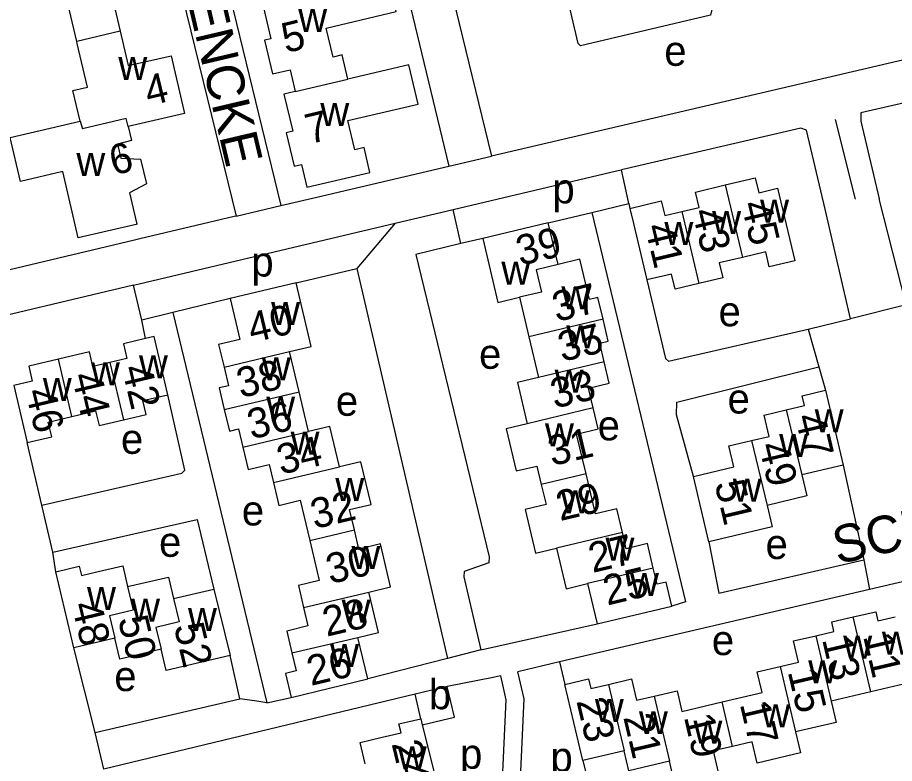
# Model space of a CAD drawing. Extents: x 157646 to 159241, y 379213 to 381217.
# Drawn here: x 158522.9 to 158640, y 380559.1 to 380658.9 of the extents above; entities that cross this region are included whole.
import ezdxf

# ---------------------------------------------------------------- set-up
doc = ezdxf.new("R2010")
doc.units = 0
for name, color, linetype in [('BLT_Basislijn', 7, 'Continuous'), ('BLT_Bebouwing', 7, 'Continuous'), ('BLT_Centroide', 7, 'Continuous'), ('BLT_Huisnummer', 7, 'Continuous'), ('BLT_Huisnummer_ tussenligend', 7, 'Continuous'), ('BLT_Onderverdeling_panden', 7, 'Continuous'), ('BLT_Straatnaam', 7, 'Continuous')]:
    doc.layers.add(name, color=color, linetype=linetype)

msp = doc.modelspace()

# ---------------------------------------------------------------- linework, layer by layer
at = {"layer": 'BLT_Basislijn'}
for p, q in [((158567.85, 380691.44), (158580.51, 380638.99)), ((158545.31, 380686.05), (158558.07, 380633.72)), ((158580.8, 380662.49), (158586.2, 380640.34)), ((158632.13, 380645.23), (158634.79, 380634.57)), ((158580.51, 380638.99), (158586.2, 380640.34)), ((158604.54, 380634.01), (158603.58, 380638.51)), ((158552.08, 380632.31), (158558.07, 380633.72)), ((158582.13, 380628.63), (158581.1, 380633.2)), ((158573.33, 380631.36), (158568.22, 380625.29)), ((158539.5, 380618.39), (158538.4, 380623.1)), ((158551.28, 380621.28), (158543.64, 380619.41)), ((158641.63, 380620.46), (158634.19, 380618.59)), ((158543.64, 380619.41), (158539.5, 380618.39)), ((158543.64, 380619.41), (158556.22, 380567.27)), ((158540.01, 380615.94), (158539.5, 380618.39)), ((158628.53, 380617.18), (158629.95, 380612.15)), ((158629.95, 380612.15), (158630.84, 380609.03)), ((158526.15, 380593.65), (158524.19, 380602.04)), ((158633.21, 380599.03), (158635.96, 380586.38)), ((158527.62, 380587.38), (158526.15, 380593.65)), ((158528.02, 380584.76), (158527.62, 380587.38)), ((158635.96, 380586.38), (158636.73, 380582.42)), ((158636.73, 380582.42), (158595.3, 380572.71)), ((158584.8, 380574.33), (158600.34, 380577.82)), ((158533.27, 380563.29), (158530.41, 380574.61)), ((158584.8, 380574.33), (158580.32, 380573.19)), ((158552.58, 380567.79), (158551.29, 380573.59)), ((158580.32, 380573.19), (158569.67, 380570.44)), ((158595.3, 380572.71), (158589.75, 380571.41)), ((158595.3, 380572.71), (158596.01, 380569.69)), ((158587.42, 380570.87), (158586.42, 380570.64)), ((158534.42, 380558.37), (158533.27, 380563.29)), ((158598.42, 380559.54), (158601.14, 380548.1))]:
    msp.add_line(p, q, dxfattribs=at)
for points in [[(158539.43, 380684.65), (158542.18, 380672.91), (158552.08, 380632.31)], [(158696.38, 380677.06), (158698.13, 380668.11), (158696.65, 380666.48), (158685.35, 380663.55), (158586.2, 380640.34)], [(158615.94, 380661.19), (158615.45, 380659.17), (158598.09, 380655.07), (158597.77, 380655.38), (158596.64, 380660.35), (158593.6, 380660.3), (158592.43, 380664.98), (158580.8, 380662.49)], [(158706.76, 380657.87), (158702.49, 380661.48), (158635.57, 380646.12), (158635.57, 380645.01), (158637.99, 380634.62)], [(158630.78, 380633.26), (158628.29, 380643.8), (158627.54, 380644.08), (158603.58, 380638.51)], [(158558.07, 380633.72), (158562.87, 380634.85), (158580.51, 380638.99)], [(158581.1, 380633.2), (158602.93, 380638.36), (158603.58, 380638.51)], [(158599.6, 380632.81), (158604.54, 380634.01)], [(158604.54, 380634.01), (158604.7, 380633.33)], [(158641.63, 380620.46), (158637.99, 380634.62)], [(158573.33, 380631.36), (158581.1, 380633.2)], [(158593.8, 380631.41), (158599.6, 380632.81)], [(158599.6, 380632.81), (158612.15, 380580.74), (158610.29, 380580.19)], [(158634.19, 380618.59), (158630.78, 380633.26)], [(158552.08, 380632.31), (158551.84, 380632.25), (158539.21, 380629.26)], [(158538.4, 380623.1), (158573.33, 380631.36)], [(158539.21, 380629.26), (158538.5, 380629.1), (158521.88, 380625.14)], [(158585.04, 380629.32), (158582.13, 380628.63)], [(158582.13, 380628.63), (158576.1, 380627.2), (158585.9, 380586.78), (158585.87, 380585.95), (158582.58, 380584.8), (158582.5, 380584.11), (158584.8, 380574.33)], [(158560.1, 380623.38), (158568.22, 380625.29)], [(158568.22, 380625.29), (158580.32, 380573.19)], [(158606.96, 380623.78), (158609.48, 380613.29), (158609.86, 380612.94), (158628.53, 380617.18)], [(158538.4, 380623.1), (158513.99, 380617.28), (158516.27, 380606.04)], [(158628.53, 380617.18), (158634.19, 380618.59)], [(158613.19, 380597.51), (158610.91, 380605.74), (158610.98, 380607.46), (158629.95, 380612.15)], [(158526.15, 380593.65), (158544.86, 380597.96), (158545.25, 380598.33), (158542.98, 380608.44)], [(158527.62, 380587.38), (158546.87, 380591.77), (158549.11, 380582.46)], [(158673, 380587.82), (158672.12, 380590.66), (158636.73, 380582.42)], [(158615.26, 380588.78), (158616.59, 380581.91), (158635.96, 380586.38)], [(158586.42, 380570.64), (158580.28, 380569.43)], [(158587.42, 380570.87), (158588.13, 380567.66), (158587.29, 380549.3), (158588.35, 380544.99)], [(158590.69, 380545.54), (158589.73, 380549.4), (158590.57, 380567.8), (158589.75, 380571.41)], [(158576, 380568.41), (158534.42, 380558.37)], [(158533.27, 380563.29), (158552.58, 380567.79)], [(158556.22, 380567.27), (158554.84, 380567.46), (158552.58, 380567.79)], [(158556.22, 380567.27), (158559.46, 380567.96)]]:
    msp.add_lwpolyline(points, dxfattribs=at)
at = {"layer": 'BLT_Bebouwing'}
for p, q in [((158538.85, 380631.22), (158538.75, 380631.2)), ((158593.8, 380631.41), (158585.04, 380629.32)), ((158560.1, 380623.38), (158551.28, 380621.28)), ((158589.94, 380621.46), (158591.2, 380616.16)), ((158591.2, 380616.16), (158592.49, 380610.74)), ((158560.52, 380608.83), (158559.24, 380614.2)), ((158561.78, 380603.52), (158560.52, 380608.83)), ((158630.84, 380609.03), (158633.21, 380599.03)), ((158522.88, 380607.57), (158524.19, 380602.04)), ((158633.21, 380599.03), (158627.65, 380597.71)), ((158615.26, 380588.78), (158613.19, 380597.51)), ((158530.41, 380574.61), (158528.02, 380584.76)), ((158549.11, 380582.46), (158551.29, 380573.59)), ((158599.06, 380583.18), (158600.34, 380577.82)), ((158600.34, 380577.82), (158610.29, 380580.19)), ((158535.87, 380575.9), (158530.41, 380574.61)), ((158569.67, 380570.44), (158568.35, 380576)), ((158559.46, 380567.96), (158569.67, 380570.44)), ((158598.42, 380559.54), (158596.01, 380569.69)), ((158642.18, 380569.97), (158636.88, 380568.73)), ((158576.78, 380565.13), (158576, 380568.41)), ((158636.88, 380568.73), (158631.58, 380567.49)), ((158603.94, 380560.85), (158598.42, 380559.54))]:
    msp.add_line(p, q, dxfattribs=at)
for points in [[(158532.82, 380673.12), (158538.49, 380674.43), (158540.29, 380666.69), (158538.41, 380666.25), (158539.28, 380662.49), (158535.54, 380661.61), (158536.6, 380657.04)], [(158530.8, 380655.65), (158528.82, 380664.15), (158532.54, 380665.01), (158531.25, 380670.55)], [(158567.04, 380650.62), (158566.27, 380653.85), (158565.05, 380653.56), (158564.13, 380657.44), (158573.47, 380659.65), (158572.23, 380664.9), (158564.1, 380662.97)], [(158560.23, 380662.07), (158555.58, 380660.97), (158556.75, 380656.01), (158555.89, 380655.81), (158556.95, 380651.32), (158559.31, 380651.87), (158560, 380648.96)], [(158536.6, 380657.04), (158537.68, 380652.42), (158543.4, 380653.75), (158545.19, 380646.03), (158537.67, 380644.28)], [(158531.25, 380645), (158530.29, 380649.1), (158532.22, 380649.55), (158530.84, 380655.38), (158530.8, 380655.65)], [(158560, 380648.96), (158558.48, 380648.6), (158559.66, 380643.65), (158558.8, 380643.44), (158559.86, 380638.97), (158560.83, 380639.2), (158561.55, 380636.17), (158569.97, 380638.16), (158569.19, 380641.46), (158567.96, 380641.17), (158567.04, 380645.07), (158576.4, 380647.28), (158575.15, 380652.54), (158567.04, 380650.62)], [(158538.75, 380631.2), (158531, 380629.4), (158528.94, 380638.26), (158523.27, 380636.94), (158521.9, 380642.83), (158531.25, 380645)], [(158537.67, 380644.28), (158538.11, 380642.42), (158536.26, 380641.94), (158536.68, 380640.07), (158539.32, 380639.94), (158540.12, 380636.63), (158537.86, 380635.4), (158538.85, 380631.22)], [(158617.45, 380636.47), (158621.45, 380637.41), (158621.92, 380635.44), (158624.43, 380636.04), (158626.73, 380626.35), (158623.33, 380625.54), (158622.86, 380627.53), (158619.74, 380626.79)], [(158611.64, 380632.94), (158613.94, 380633.48), (158613.45, 380635.52), (158617.45, 380636.47)], [(158604.7, 380633.33), (158608.89, 380634.33), (158609.35, 380632.4), (158611.64, 380632.94)], [(158604.7, 380633.33), (158605.17, 380631.32), (158606.96, 380623.78)], [(158595.13, 380625.86), (158593.8, 380631.41)], [(158585.04, 380629.32), (158587.08, 380620.78), (158589.94, 380621.46)], [(158619.74, 380626.79), (158616.65, 380626.06), (158617.12, 380624.08), (158613.92, 380623.32)], [(158601.11, 380618.52), (158600.42, 380621.45), (158599.3, 380621.18), (158598.02, 380626.55), (158595.13, 380625.86)], [(158613.92, 380623.32), (158610.74, 380622.56), (158610.26, 380624.56), (158606.96, 380623.78)], [(158559.24, 380614.2), (158562.12, 380614.89), (158560.1, 380623.38)], [(158551.28, 380621.28), (158552.58, 380615.82), (158549.76, 380615.15), (158550.48, 380612.12)], [(158601.27, 380612.83), (158600.67, 380615.33), (158601.81, 380615.6), (158601.11, 380618.52)], [(158542.98, 380608.44), (158541.14, 380616.21), (158540.01, 380615.94)], [(158540.01, 380615.94), (158537.03, 380615.23), (158537.5, 380613.27), (158535.23, 380612.73)], [(158535.23, 380612.73), (158532.96, 380612.19), (158532.49, 380614.17), (158528.35, 380613.18)], [(158528.35, 380613.18), (158524.39, 380612.24), (158524.86, 380610.25), (158522.38, 380609.67), (158522.88, 380607.57)], [(158599.79, 380606.66), (158599.15, 380609.32), (158601.95, 380609.99), (158601.27, 380612.83)], [(158550.48, 380612.12), (158551.07, 380609.63), (158549.84, 380609.34), (158550.52, 380606.45)], [(158592.49, 380610.74), (158589.67, 380610.07), (158590.99, 380604.55)], [(158537.05, 380605.07), (158540.08, 380605.79), (158539.64, 380607.65), (158542.98, 380608.44)], [(158625.58, 380606.42), (158628.04, 380607), (158627.73, 380608.29), (158630.84, 380609.03)], [(158530.16, 380605.54), (158533.33, 380606.29), (158533.81, 380604.3), (158537.05, 380605.07)], [(158550.52, 380606.45), (158551.21, 380603.57), (158552.4, 380603.86), (158552.98, 380601.42)], [(158598.85, 380597.84), (158597.58, 380603.18), (158600.46, 380603.86), (158599.79, 380606.66)], [(158620.97, 380602.32), (158623.32, 380602.87), (158622.64, 380605.72), (158625.58, 380606.42)], [(158524.19, 380602.04), (158527.46, 380602.82), (158526.99, 380604.78), (158530.16, 380605.54)], [(158590.99, 380604.55), (158588.18, 380603.89), (158589.53, 380598.24), (158592.27, 380598.9), (158592.86, 380596.42)], [(158565.91, 380598.8), (158564.63, 380604.19), (158561.78, 380603.52)], [(158613.19, 380597.51), (158618.59, 380598.79), (158617.92, 380601.6), (158620.97, 380602.32)], [(158552.98, 380601.42), (158553.7, 380598.42), (158556.52, 380599.09), (158557.09, 380596.7)], [(158567.89, 380590.37), (158567.24, 380593.09), (158570.13, 380593.77), (158568.77, 380599.48), (158565.91, 380598.8)], [(158603.7, 380590.03), (158602.95, 380593.18), (158600.12, 380592.51), (158598.85, 380597.84)], [(158627.65, 380597.71), (158628.32, 380594.9), (158623.03, 380593.64)], [(158557.09, 380596.7), (158557.81, 380593.64), (158560.66, 380594.32), (158561.94, 380588.95)], [(158592.86, 380596.42), (158593.5, 380593.74), (158590.72, 380593.08), (158592.11, 380587.26), (158594.89, 380587.92)], [(158623.03, 380593.64), (158623.71, 380590.79), (158615.26, 380588.78)], [(158569.82, 380582.04), (158572.73, 380582.74), (158571.37, 380588.48), (158568.5, 380587.8), (158567.89, 380590.37)], [(158607.83, 380585.27), (158607.06, 380588.53), (158604.22, 380587.85), (158603.7, 380590.03)], [(158561.94, 380588.95), (158563.21, 380583.59), (158560.41, 380582.92), (158561.11, 380579.97)], [(158594.89, 380587.92), (158596.18, 380582.49), (158599.06, 380583.18)], [(158528.02, 380584.76), (158531.13, 380585.5), (158531.42, 380584.26), (158533.68, 380584.79)], [(158533.68, 380584.79), (158536.94, 380585.56), (158537.6, 380582.78)], [(158610.29, 380580.19), (158609.53, 380583.38), (158608.35, 380583.1), (158607.83, 380585.27)], [(158537.6, 380582.78), (158543.05, 380584.06), (158543.73, 380581.19)], [(158543.73, 380581.19), (158549.11, 380582.46)], [(158568.35, 380576), (158571.1, 380576.65), (158569.82, 380582.04)], [(158561.11, 380579.97), (158561.69, 380577.52), (158558.86, 380576.84), (158559.56, 380573.91)], [(158629.53, 380576.22), (158631.96, 380576.79), (158631.67, 380578.06), (158634.54, 380578.73)], [(158634.54, 380578.73), (158637.54, 380579.43), (158637.82, 380578.23), (158640.12, 380578.76)], [(158542.09, 380574.4), (158536.54, 380573.08), (158535.87, 380575.9)], [(158624.77, 380572.09), (158627.24, 380572.67), (158626.57, 380575.53), (158629.53, 380576.22)], [(158551.29, 380573.59), (158542.76, 380571.57), (158542.09, 380574.4)], [(158559.56, 380573.91), (158560.13, 380571.52), (158558.7, 380571.18), (158559.46, 380567.96)], [(158617.04, 380567.36), (158622.36, 380568.61), (158621.71, 380571.37), (158624.77, 380572.09)], [(158580.28, 380569.43), (158576, 380568.41)], [(158576.97, 380564.32), (158581.25, 380565.34), (158580.28, 380569.43)], [(158596.01, 380569.69), (158599.17, 380570.44), (158599.48, 380569.15), (158601.84, 380569.71)], [(158601.84, 380569.71), (158604.92, 380570.44), (158605.58, 380567.59), (158607.94, 380568.14)], [(158607.94, 380568.14), (158611, 380568.85), (158611.64, 380566.1), (158617.04, 380567.36)], [(158631.58, 380567.49), (158632.25, 380564.63), (158626.82, 380563.36)], [(158571.62, 380562.64), (158574.13, 380563.24), (158573.84, 380564.43), (158576.78, 380565.13)], [(158576.97, 380564.32), (158579.23, 380555.27)], [(158569.35, 380559.08), (158568.67, 380561.93), (158571.62, 380562.64)], [(158626.82, 380563.36), (158627.48, 380560.56), (158621.7, 380559.2), (158621.04, 380562.04), (158618.43, 380561.43)], [(158618.43, 380561.43), (158615.82, 380560.82), (158616.49, 380557.93), (158615.52, 380557.71), (158610.65, 380556.57), (158609.98, 380559.43)], [(158609.98, 380559.43), (158604.57, 380558.17), (158603.94, 380560.85)]]:
    msp.add_lwpolyline(points, dxfattribs=at)
at = {"layer": 'BLT_Onderverdeling_panden'}
for p, q in [((158536.6, 380657.04), (158530.8, 380655.65)), ((158560, 380648.96), (158567.04, 380650.62)), ((158531.25, 380645), (158531.56, 380643.96)), ((158617.45, 380636.47), (158619.74, 380626.79)), ((158611.64, 380632.94), (158613.92, 380623.32)), ((158601.11, 380618.52), (158591.2, 380616.16)), ((158550.48, 380612.12), (158559.24, 380614.2)), ((158530.16, 380605.54), (158528.35, 380613.18)), ((158535.23, 380612.73), (158537.05, 380605.07)), ((158601.27, 380612.83), (158592.49, 380610.74)), ((158550.52, 380606.45), (158560.52, 380608.83)), ((158599.79, 380606.66), (158590.99, 380604.55)), ((158625.58, 380606.42), (158627.65, 380597.71)), ((158552.98, 380601.42), (158561.78, 380603.52)), ((158620.97, 380602.32), (158623.03, 380593.64)), ((158557.09, 380596.7), (158565.91, 380598.8)), ((158598.85, 380597.84), (158592.86, 380596.42)), ((158561.94, 380588.95), (158567.89, 380590.37)), ((158603.7, 380590.03), (158594.89, 380587.92)), ((158607.83, 380585.27), (158599.06, 380583.18)), ((158561.11, 380579.97), (158569.82, 380582.04)), ((158636.88, 380568.73), (158634.54, 380578.73)), ((158559.56, 380573.91), (158568.35, 380576)), ((158629.53, 380576.22), (158631.58, 380567.49)), ((158624.77, 380572.09), (158626.82, 380563.36)), ((158601.84, 380569.71), (158603.94, 380560.85)), ((158607.94, 380568.14), (158609.98, 380559.43)), ((158618.43, 380561.43), (158617.04, 380567.36))]:
    msp.add_line(p, q, dxfattribs=at)
for points in [[(158537.67, 380644.28), (158537.42, 380645.34), (158531.56, 380643.96)], [(158595.13, 380625.86), (158592.18, 380625.15), (158592.89, 380622.16), (158589.94, 380621.46)], [(158537.6, 380582.78), (158538.35, 380579.63), (158535.17, 380578.88), (158535.87, 380575.9)], [(158543.73, 380581.19), (158544.47, 380578.07), (158541.39, 380577.34), (158542.09, 380574.4)], [(158576.78, 380565.13), (158576.97, 380564.32)]]:
    msp.add_lwpolyline(points, dxfattribs=at)

# ---------------------------------------------------------------- texts
at = {"layer": 'BLT_Centroide'}
for s, p in [('w', (158560.39, 380656.94)), ('e', (158609.3, 380652.4)), ('w', (158536.36, 380650.5)), ('w', (158563.34, 380644.34)), ('w', (158530.75, 380637.69)), ('p', (158594.35, 380634.01)), ('w', (158622.09, 380631.42)), ('w', (158615.69, 380629.91)), ('w', (158609.31, 380628.45)), ('p', (158554.13, 380624.23)), ('w', (158587.53, 380623.13)), ('w', (158595.55, 380619.84)), ('w', (158556.77, 380617.75)), ('e', (158616.55, 380617.58)), ('w', (158596.2, 380614.62)), ('e', (158584.55, 380611.9)), ('w', (158532.7, 380609.7)), ('w', (158539.11, 380610.64)), ('w', (158555.53, 380610.34)), ('w', (158594.65, 380608.69)), ('w', (158526.27, 380607.61)), ('w', (158556.12, 380605.12)), ('e', (158565.42, 380605.62)), ('e', (158617.75, 380605.92)), ('w', (158629.39, 380603.41)), ('w', (158593.36, 380601.53)), ('e', (158600.4, 380602.33)), ('e', (158536.71, 380600.53)), ('w', (158559.37, 380600.44)), ('w', (158624.64, 380600.11)), ('w', (158565.35, 380594.22)), ('w', (158618.45, 380594.14)), ('w', (158595.48, 380592.56)), ('e', (158552.86, 380590.96)), ('e', (158541.8, 380586.77)), ('w', (158601.44, 380586.25)), ('e', (158622.83, 380586.47)), ('w', (158567.5, 380585.16)), ('w', (158604.71, 380581.53)), ('w', (158532.17, 380579.64)), ('w', (158538.06, 380578.08)), ('w', (158545.66, 380576.84)), ('w', (158566.19, 380577.97)), ('e', (158615.65, 380573.63)), ('w', (158638.36, 380573.7)), ('w', (158633.2, 380573.14)), ('w', (158564.65, 380572.03)), ('w', (158628.52, 380569.86)), ('e', (158535.82, 380568.82)), ('b', (158577.85, 380566.39)), ('w', (158600.02, 380564.7)), ('w', (158622.25, 380563.97)), ('w', (158605.91, 380563.06)), ('w', (158613.19, 380561.81)), ('w', (158573.69, 380558.34)), ('p', (158582.01, 380558.44)), ('p', (158594.09, 380558.02))]:
    msp.add_text(s, height=4, dxfattribs=at).set_placement(p)
at = {"layer": 'BLT_Huisnummer'}
for s, rotation, p in [('5', 13.692, (158558.72, 380654.08)), ('4', 13.692, (158540.41, 380647.01)), ('7', 13.692, (158561.89, 380641.91)), ('6', 13.692, (158535.72, 380637.73)), ('45', 283.3329, (158619.54, 380633.92)), ('39', 13.4246, (158590.04, 380625.66)), ('41', 283.3326, (158606.68, 380630.9)), ('37', 13.4186, (158594.88, 380618.15)), ('40', 13.3608, (158554.2, 380615.35)), ('42', 283.3551, (158536.8, 380612)), ('33', 13.4107, (158594.63, 380606.57)), ('46', 283.339, (158523.93, 380608.86)), ('47', 283.3358, (158626.75, 380605.47)), ('34', 13.3608, (158558.07, 380597.73)), ('29', 13.352, (158595.37, 380591.53)), ('51', 283.325, (158616, 380596.57)), ('30', 13.3608, (158564.65, 380583.11)), ('25', 13.4164, (158601.66, 380580.24)), ('48', 283.3403, (158530.1, 380580.34)), ('52', 283.3597, (158543.76, 380577.49)), ('13', 283.1974, (158630.36, 380575.74)), ('26', 13.3608, (158562.08, 380569.5)), ('23', 283.1974, (158597.54, 380567.5)), ('17', 283.1974, (158619.37, 380567.09)), ('24', 283.4492, (158572.85, 380561.8))]:
    msp.add_text(s, height=4, rotation=rotation, dxfattribs=at).set_placement(p)
at = {"layer": 'BLT_Huisnummer_ tussenligend'}
for s, rotation, p in [('43', 283.3326, (158613, 380632.92)), ('35', 13.4107, (158595.63, 380612.81)), ('38', 13.3608, (158552.7, 380607.97)), ('44', 283.3551, (158530.09, 380610.98)), ('36', 13.3608, (158554.13, 380602.45)), ('31', 13.352, (158594.3, 380598.88)), ('49', 283.3358, (158621.9, 380601.66)), ('32', 13.3608, (158562.57, 380590.47)), ('27', 13.4164, (158599.71, 380584.6)), ('28', 13.3608, (158564.18, 380576.07)), ('50', 283.3403, (158536.29, 380578.45)), ('11', 283.1974, (158635.84, 380576.15)), ('15', 283.1974, (158625.77, 380571.42)), ('21', 283.1974, (158603.8, 380565.34)), ('19', 283.1974, (158611.9, 380565.38))]:
    msp.add_text(s, height=4, rotation=rotation, dxfattribs=at).set_placement(p)
at = {"layer": 'BLT_Straatnaam'}
for s, rotation, p in [('DE KLENCKE', 283.2468, (158541.13, 380679.88)), ('SCHATZENBURG', 13.0913, (158632.45, 380585.74))]:
    msp.add_text(s, height=5, rotation=rotation, dxfattribs=at).set_placement(p)

doc.saveas('drawing.dxf')
